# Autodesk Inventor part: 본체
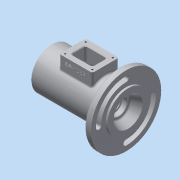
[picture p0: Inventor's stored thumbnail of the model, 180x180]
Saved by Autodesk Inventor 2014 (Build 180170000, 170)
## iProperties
Created: 2017-05
Part Number: 본체
Material: 알루미늄 6061
Document SubType Name: Modeling
Designer: SCD-A15
Density: 2.71 g/cm^3
Appearance: 알루미늄 - 평지
Author: SCD-A15
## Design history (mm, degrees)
sketch "스케치1"
  geometry: L1 (-57.5, 0)-(57.5, 0); L2 (-57.5, 0)-(-57.5, 31); L3 (-57.5, 31)-(57.5, 31); L4 (57.5, 31)-(57.5, 0); 2 further points
  constraints: 8 end point, 2 perpendicular, 1 coincident, 1 horizontal, 1 midpoint, 1 parallel
  dimensions: "d0" = 115 distance of L1.start L1.end; "d1" = 62 diameter of L3 L1
revolve "회전1" sketch "스케치1" stored, may be unused: angle "d2" = 90 deg
sketch "스케치2"
  geometry: L1 (-57.5, 0)-(57.5, 0); L2 (57.5, 0)-(57.5, 22); L3 (57.5, 22)-(45.318, 16.779); L4 (43.5, 14.022)-(43.5, 12.904); L5 (42.8, 12.5)-(36.5, 12.5); L6 (36.2, 12.2)-(36.2, 10); L7 (36.2, 10)-(33.5, 10); L8 (33.5, 10)-(33.5, 13.5); L9 (30.5, 16.5)-(28.5, 16.5); L10 (28.5, 16.5)-(28.5, 17.2); L11 (28.2, 17.5)-(18.5, 17.5); L12 (17.5, 18.5)-(17.5, 23); L13 (14.5, 26)-(-17.5, 26); L14 (-20.5, 23)-(-20.5, 18.5); L15 (-21.5, 17.5)-(-31.5, 17.5); L16 (-31.5, 17.5)-(-31.5, 18.5); L17 (-31.5, 18.5)-(-33.25, 18.5); L18 (-33.25, 18.5)-(-33.25, 17.5); L19 (-33.25, 17.5)-(-36.5, 17.5); L20 (-36.5, 17.5)-(-36.5, 20); L21 (-36.5, 20)-(-45.5, 20); L22 (-45.5, 20)-(-45.5, 24); L23 (-45.5, 24)-(-48.5, 24); L24 (-48.5, 24)-(-48.5, 0); L25 (42.8, 12.5)-(43.5, 12.904); L26 (-20.5, 18.5)-(-21.5, 17.5); L27 (17.5, 18.5)-(18.5, 17.5); A1 r 0.3 centre (36.5, 12.2) between (36.5, 12.5) and (36.2, 12.2); A2 r 0.3 centre (28.2, 17.2) between (28.5, 17.2) and (28.2, 17.5); A3 r 3 centre (30.5, 13.5) between (33.5, 13.5) and (30.5, 16.5); A4 r 3 centre (14.5, 23) between (17.5, 23) and (14.5, 26); A5 r 3 centre (-17.5, 23) between (-17.5, 26) and (-20.5, 23); A6 r 3 centre (46.5, 14.022) between (45.318, 16.779) and (43.5, 14.022); 11 further points
  constraints: 54 end point, 19 parallel, 19 point on line, 12 point on circle, 12 tangent, 6 centre point, 3 equal radius, 3 perpendicular, 1 coincident, 1 horizontal, 1 midpoint
  dimensions: "d3" = 115 distance of L1.start L1.end; "d4" = 44 diameter of L2.end L1; "d5" = 32 diameter of point (43.5, 16) L1; "d6" = 25 diameter of L5 L1; "d7" = 20 diameter of L7 L1; "d8" = 33 diameter of L9 L1; "d9" = 35 diameter of L11 L1; "d10" = 52 diameter of L13 L1; "d11" = 35 diameter of L15 L1; "d12" = 37 diameter of L17 L1; "d13" = 35 diameter of L19 L1; "d14" = 40 diameter of L21 L1; "d15" = 48 diameter of L23 L1; "d16" = 14 distance between parallel lines of L2 L4; "d18" = 2.7 distance between parallel lines of L6 L8; "d19" = 10 distance between parallel lines of L8 L4; "d20" = 5 distance between parallel lines of L10 L8; "d21" = 11 distance between parallel lines of L12 L10; "d22" = 38 distance between parallel lines of L14 L12; "d23" = 11 distance from line of L16.end L14; "d24" = 1.75 distance between parallel lines of L18 L16; "d25" = 3 distance between parallel lines of L22 L24; "d26" = 21 distance from line of L20 L1.start; "d27" = 9 distance from line of L1.start L24; "d38" = 0.7 distance of L5.start point (43.5, 12.5); "d39" = 30 deg angle of L5 L25; "d40" = 0.3 radius of A1; "d41" = 3 radius of A3; "d42" = 1 distance of L14.end point (-20.5, 17.5); "d43" = 1 distance of L15.start point (-20.5, 17.5) (= d42); "d44" = 1 distance of L12.start point (17.5, 17.5) (= d42); "d45" = 1 distance of L11.end point (17.5, 17.5) (= d44); "d46" = 3 radius of A6
hole "구멍1" diameter "d31" = 40.4; stored, may be unused: countersink angle "d35" = 90 deg, drill point angle "d37" = 118 deg; dims "d29" = 10, "d30" = 10, "d32" = 9, "d33" = 4, "d34" = 2, "d36" = 9
chamfer "모따기1" distance "d47" = 1; stored, may be unused: second distance "d48" = 2, angle "d49" = 45 deg
node "작업 평면1"
sketch "스케치4"
  geometry: C1 r 53 at (0, 0); A1 r 45.5 centre (0, 0) between (0, 45.5) and (-45.5, 0); A2 r 45.5 centre (0, 0) between (0, -45.5) and (45.5, 0); A3 r 37.5 centre (0, 0) between (0, 37.5) and (-37.5, 0); A4 r 37.5 centre (0, 0) between (0, -37.5) and (37.5, 0); A5 r 4 centre (0, 41.5) between (0, 37.5) and (0, 45.5); A6 r 4 centre (-41.5, 0) between (-45.5, 0) and (-37.5, 0); A7 r 4 centre (41.5, 0) between (45.5, 0) and (37.5, 0); A8 r 4 centre (0, -41.5) between (0, -37.5) and (0, -45.5); 3 further points
  constraints: 16 point on circle, 9 centre point, 5 coincident
  dimensions: "d52" = 106 diameter of C1; "d55" = 45.5 radius of A1; "d56" = 37.5 radius of A3; "d57" = 37.5 radius of A4; "d58" = 45.5 radius of A2; "d59" = 4 radius of A5
extrude "돌출1" join sketch "스케치4" distance "d61" = 10; taper "d62" = 0 deg
node "작업 평면2"
sketch "스케치5"
  geometry: L1 (57.5, 31)-(57.5, -31) reference; L2 (57.5, 0)-(1.5, 0); L3 (26.5, -20)-(-23.5, -20); L4 (-23.5, -20)-(-23.5, 20); L5 (-23.5, 20)-(26.5, 20); L6 (26.5, 20)-(26.5, -20); L7 (26.5, -20)-(-23.5, 20); L8 (-23.5, -20)-(26.5, 20); L9 (17.5, -11)-(-14.5, -11); L10 (-14.5, -11)-(-14.5, 11); L11 (-14.5, 11)-(17.5, 11); L12 (17.5, 11)-(17.5, -11); L13 (17.5, -11)-(-14.5, 11); L14 (-14.5, -11)-(17.5, 11); 2 further points
  constraints: 26 end point, 6 midpoint, 4 parallel, 3 perpendicular, 2 horizontal
  dimensions: "d64" = 56 distance of L2.end L2.start; "d65" = 50 distance of L4.end L5.end; "d66" = 40 distance of L3.end L4.end; "d67" = 32 distance of L10.end L11.end; "d68" = 22 distance of L9.end L10.end
extrude "돌출2" join sketch "스케치5" distance "d69" = 30; taper "d70" = 0 deg
revolve "회전3" stored, may be unused: angle "d71" = 90 deg
extrude "돌출3" cut sketch "스케치5" stored distance "d72" = 30; taper "d73" = 0 deg
fillet "모깎기1" dims "d74" = 3
chamfer "모따기2" distance "d75" = 1; stored, may be unused: second distance "d76" = 2, angle "d77" = 45 deg
sketch "스케치6"
  geometry: L1 (-14.5, -12)-(11.5, -12) reference; L2 (11.5, 12)-(-14.5, 12) reference; L3 (-1.5, 12)-(-1.5, -12); L4 (-1.5, 0)-(-1.5, -15.5); L5 (-1.5, -15.5)-(19, -15.5); 1 further point
  constraints: 6 end point, 3 midpoint, 1 perpendicular, 1 point on line
  dimensions: "d80" = 15.5 distance of L4.start L4.end; "d81" = 20.5 distance of L4.end L5.end
hole "구멍2" sketch "스케치6" at (19, -15.5) diameter "d82" = 2.5; stored, may be unused: countersink angle "d86" = 90 deg, drill point angle "d88" = 118 deg; dims "d83" = 6, "d84" = 4, "d85" = 2, "d87" = 8
node "작업 평면3"
sketch "스케치7"
  geometry: L1 (-34, -75)-(-34, -13) reference; L2 (-34, -13)-(-34, 0); L3 (-34, 0)-(22, 0); L4 (22, 0)-(22, -8); 2 further points
  constraints: 6 end point, 2 perpendicular, 1 coincident, 1 collinear, 1 other
  dimensions: "d101" = 56 distance of L2.end L3.end; "d102" = 8 distance of L3.end L4.end; "d103" = 13 distance of L1.end L2.end
feature "엠보싱1" sketch "스케치7" dims "d0" = 115, "d1" = 62, "d104" = 0.5, "d105" = 0
node "솔리드1"
pattern_linear "직사각형 패턴1" dims "d91" = 41, "d94" = 31
other parameters: "d50" = -3, "d53" = 75, "d54" = 91, "d63" = 44
